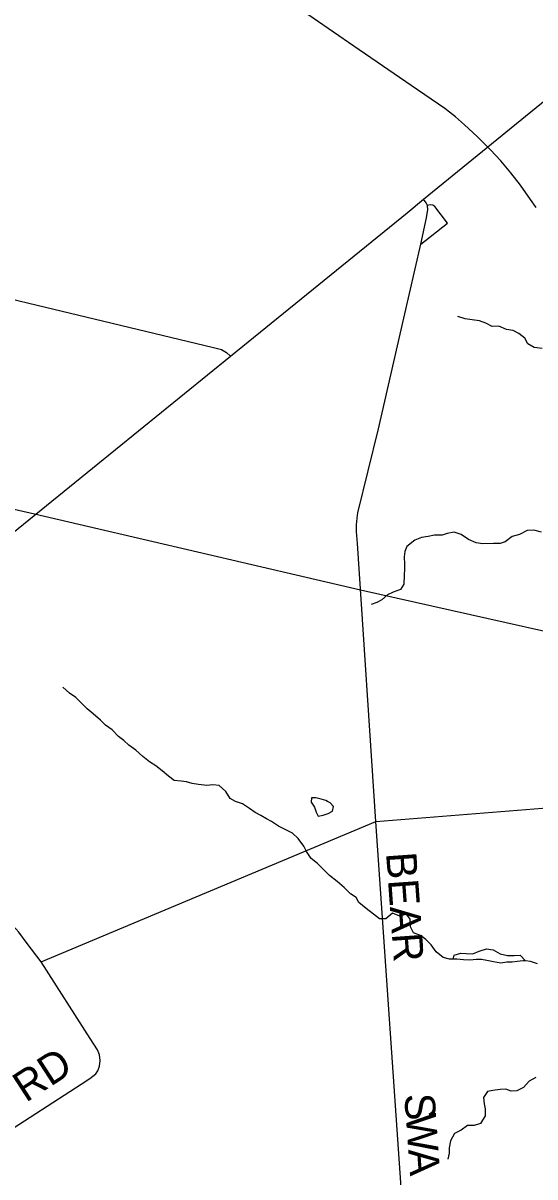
# Model space of a CAD drawing. Extents: x 0 to 34, y 0 to 22.
# Drawn here: x 4.289 to 4.77, y 14.924 to 16.008 of the extents above; entities that cross this region are included whole.
import ezdxf

# ---------------------------------------------------------------- set-up
doc = ezdxf.new("R2010")
doc.units = 0
for name, color, linetype in [('GM_X_County_Road', 7, 'Continuous'), ('GM_X_County_Road_Text', 7, 'Continuous'), ('GM_X_Minor_Lake', 7, 'Continuous'), ('GM_X_Minor_River', 7, 'Continuous'), ('GM_X_Rail_Line', 7, 'Continuous'), ('GM_X_State_Route', 7, 'Continuous'), ('GM_X_Township_Road', 7, 'Continuous')]:
    doc.layers.add(name, color=color, linetype=linetype)

msp = doc.modelspace()

# ---------------------------------------------------------------- linework, layer by layer
at = {"layer": 'GM_X_County_Road'}
for points in [[(3.1492, 15.7812), (3.4013, 15.9472), (3.4056, 15.9484), (3.4107, 15.9484), (3.4889, 15.9308), (3.6071, 15.9041), (3.932, 15.83), (4.1105, 15.7887), (4.468, 15.7031), (4.4755, 15.701), (4.4802, 15.6984), (4.484, 15.6949)], [(4.6473, 14.8731), (4.6205, 15.2578), (4.6033, 15.5187), (4.6026, 15.53), (4.6026, 15.5364), (4.603, 15.5427), (4.6038, 15.5476), (4.6232, 15.6265), (4.6469, 15.7305), (4.663, 15.7999), (4.6681, 15.8246), (4.6689, 15.8288), (4.6695, 15.8322), (4.6692, 15.8363), (4.668, 15.8388), (4.6654, 15.8422)], [(4.306, 15.1259), (4.293, 15.1432), (4.2852, 15.1538), (4.2795, 15.1601), (4.2699, 15.1679), (4.2618, 15.1749), (4.0515, 15.344)], [(3.7386, 14.6201), (3.9241, 14.7398), (4.024, 14.8043), (4.3438, 15.011), (4.352, 15.0164), (4.3575, 15.0207), (4.3594, 15.0236), (4.361, 15.0279), (4.3615, 15.0333), (4.361, 15.0387), (4.3591, 15.0433), (4.3522, 15.0538), (4.306, 15.1259), (4.6205, 15.2578), (4.8635, 15.2772), (5.1173, 15.2978), (5.2791, 15.3117)]]:
    msp.add_lwpolyline(points, dxfattribs=at)
at = {"layer": 'GM_X_Minor_Lake'}
for points in [[(4.5753, 15.2766), (4.5735, 15.2774), (4.5693, 15.2786), (4.5642, 15.2799), (4.5602, 15.2801), (4.56, 15.2758), (4.5629, 15.2712), (4.5646, 15.2666), (4.5664, 15.2628)], [(4.5664, 15.2628), (4.5712, 15.2638), (4.5759, 15.2651), (4.5799, 15.2675), (4.581, 15.2717), (4.5778, 15.2753), (4.5753, 15.2766)]]:
    msp.add_lwpolyline(points, dxfattribs=at)
at = {"layer": 'GM_X_Minor_River'}
for points in [[(4.7769, 15.7021), (4.7695, 15.703), (4.7636, 15.7063), (4.7608, 15.7116), (4.7549, 15.7162), (4.7498, 15.7189), (4.7434, 15.72), (4.7362, 15.7229), (4.7301, 15.7227), (4.7241, 15.7258), (4.718, 15.7279), (4.7112, 15.7289), (4.7046, 15.73), (4.6978, 15.7321)], [(4.7764, 15.5294), (4.7691, 15.5315), (4.7628, 15.531), (4.7558, 15.5272), (4.7488, 15.5255), (4.7423, 15.5204), (4.7374, 15.5188), (4.7311, 15.519), (4.7213, 15.5186), (4.7148, 15.5194), (4.7078, 15.5225), (4.7009, 15.5272), (4.6942, 15.5295), (4.6876, 15.5282), (4.6829, 15.5267), (4.6758, 15.5266), (4.6698, 15.5255), (4.6635, 15.5245), (4.6573, 15.5221), (4.6497, 15.516), (4.6479, 15.5113), (4.6474, 15.5062), (4.6475, 15.4995), (4.6477, 15.4948), (4.6473, 15.4891), (4.6471, 15.4806), (4.6438, 15.4755), (4.637, 15.4732), (4.6315, 15.4706), (4.6264, 15.4658), (4.6215, 15.4634), (4.6163, 15.4615)], [(4.3788, 15.3376), (4.3729, 15.3437), (4.3665, 15.3481), (4.3618, 15.353), (4.355, 15.3589), (4.3494, 15.3637), (4.3445, 15.3685), (4.3388, 15.3742), (4.3328, 15.3782), (4.3266, 15.384)], [(4.6934, 15.1284), (4.6899, 15.1285), (4.6838, 15.13), (4.6774, 15.1354), (4.6727, 15.142), (4.6676, 15.147), (4.6627, 15.1508), (4.6561, 15.1531), (4.6533, 15.1587), (4.6528, 15.1659), (4.6494, 15.1708), (4.6433, 15.1688), (4.6363, 15.1715), (4.63, 15.1664), (4.6242, 15.1662), (4.6185, 15.1706), (4.6117, 15.176), (4.6047, 15.1817), (4.6023, 15.1864), (4.5968, 15.1897), (4.591, 15.1958), (4.5842, 15.2013), (4.5772, 15.2069), (4.5717, 15.2124), (4.5657, 15.2183), (4.56, 15.2229), (4.5555, 15.2296), (4.5529, 15.2347), (4.5478, 15.2418), (4.5422, 15.2467), (4.5293, 15.2533), (4.5227, 15.2577), (4.5178, 15.2602), (4.5127, 15.2634), (4.5072, 15.2663), (4.5019, 15.2699), (4.4953, 15.2743), (4.4887, 15.2766), (4.4836, 15.2793), (4.4797, 15.2858), (4.4734, 15.2915), (4.4674, 15.2921), (4.4617, 15.2916), (4.4539, 15.2924), (4.4481, 15.2934), (4.4428, 15.2949), (4.4377, 15.2955), (4.4312, 15.2963), (4.4258, 15.3003), (4.4197, 15.3053), (4.4139, 15.3101), (4.408, 15.3139), (4.4018, 15.3188), (4.3952, 15.3246), (4.3886, 15.3295), (4.3837, 15.3337), (4.3788, 15.3376)], [(4.6934, 15.1284), (4.6941, 15.1321), (4.7005, 15.1341), (4.7054, 15.1337), (4.7119, 15.1335), (4.7179, 15.1359), (4.7246, 15.138), (4.731, 15.1372), (4.7374, 15.1335), (4.7444, 15.132), (4.7505, 15.132), (4.7564, 15.1321), (4.7614, 15.1267)], [(4.7614, 15.1267), (4.7592, 15.127), (4.7535, 15.1261), (4.7488, 15.1255), (4.7438, 15.1255), (4.738, 15.1248), (4.7312, 15.1258), (4.7251, 15.1272), (4.72, 15.1281), (4.7153, 15.128), (4.709, 15.1276), (4.7029, 15.1278), (4.6969, 15.1283), (4.6934, 15.1284)], [(4.7726, 15.1239), (4.766, 15.1262), (4.7614, 15.1267)], [(4.7709, 15.0174), (4.7647, 15.0137), (4.7595, 15.0078), (4.7531, 15.0046), (4.7478, 15.0045), (4.7427, 15.0062), (4.7374, 15.006), (4.7305, 15.0049), (4.7256, 15.004), (4.7218, 14.9985), (4.7223, 14.9926), (4.7233, 14.9877), (4.7234, 14.9811), (4.719, 14.9739), (4.713, 14.9722), (4.7067, 14.9722), (4.7008, 14.9679), (4.6947, 14.9647), (4.6909, 14.9579), (4.6894, 14.9511), (4.6895, 14.9463), (4.6882, 14.9406)]]:
    msp.add_lwpolyline(points, dxfattribs=at)
at = {"layer": 'GM_X_Rail_Line'}
for points in [[(4.7713, 15.8344), (4.766, 15.8421), (4.7567, 15.8553), (4.7475, 15.8671), (4.7382, 15.8783), (4.7285, 15.8886), (4.716, 15.9011), (4.704, 15.9122), (4.6954, 15.9195), (4.69, 15.9239), (4.6854, 15.9273), (4.6538, 15.949), (4.6001, 15.986), (4.5426, 16.0253)], [(2.8725, 15.857), (2.9115, 15.8579), (2.9613, 15.8516), (2.9946, 15.8445), (3.2081, 15.795), (3.7492, 15.6705), (3.9302, 15.6314), (4.3, 15.5466), (4.6063, 15.4754), (4.9134, 15.4063), (4.9924, 15.381), (5.0264, 15.3654), (5.0626, 15.3427), (5.087, 15.3222), (5.1229, 15.2868)]]:
    msp.add_lwpolyline(points, dxfattribs=at)
at = {"layer": 'GM_X_State_Route'}
msp.add_line((4.65, 15.8296), (4.6654, 15.8422), dxfattribs=at)
for points in [[(4.6654, 15.8422), (4.8034, 15.9544), (4.817, 15.9653)], [(3.5274, 14.752), (3.5627, 14.8175), (3.5752, 14.841), (3.5839, 14.8554), (3.6777, 15.0303), (3.6875, 15.0456), (3.6987, 15.0573), (3.7393, 15.091), (3.7947, 15.1352), (4.0515, 15.344), (4.484, 15.6949), (4.65, 15.8296)]]:
    msp.add_lwpolyline(points, dxfattribs=at)
at = {"layer": 'GM_X_Township_Road'}
msp.add_lwpolyline([(4.663, 15.7999), (4.688, 15.8198), (4.6761, 15.8353), (4.6742, 15.8368), (4.6717, 15.837), (4.6692, 15.8363)], dxfattribs=at)

# ---------------------------------------------------------------- texts
at = {"layer": 'GM_X_County_Road_Text'}
for s, height, rotation, p in [('BEAR', 0.02841, 274.123, (4.6302, 15.2281)), ('RD', 0.02841, 33.0029, (4.2917, 14.9933)), ('S', 0.0284, 274.1134, (4.6473, 15.0014)), ('W', 0.0284, 274.112, (4.6487, 14.9823)), ('A', 0.0284, 274.1113, (4.651, 14.9495))]:
    msp.add_text(s, height=height, rotation=rotation, dxfattribs=at).set_placement(p)

doc.saveas('drawing.dxf')
